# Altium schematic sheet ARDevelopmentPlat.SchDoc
size A3
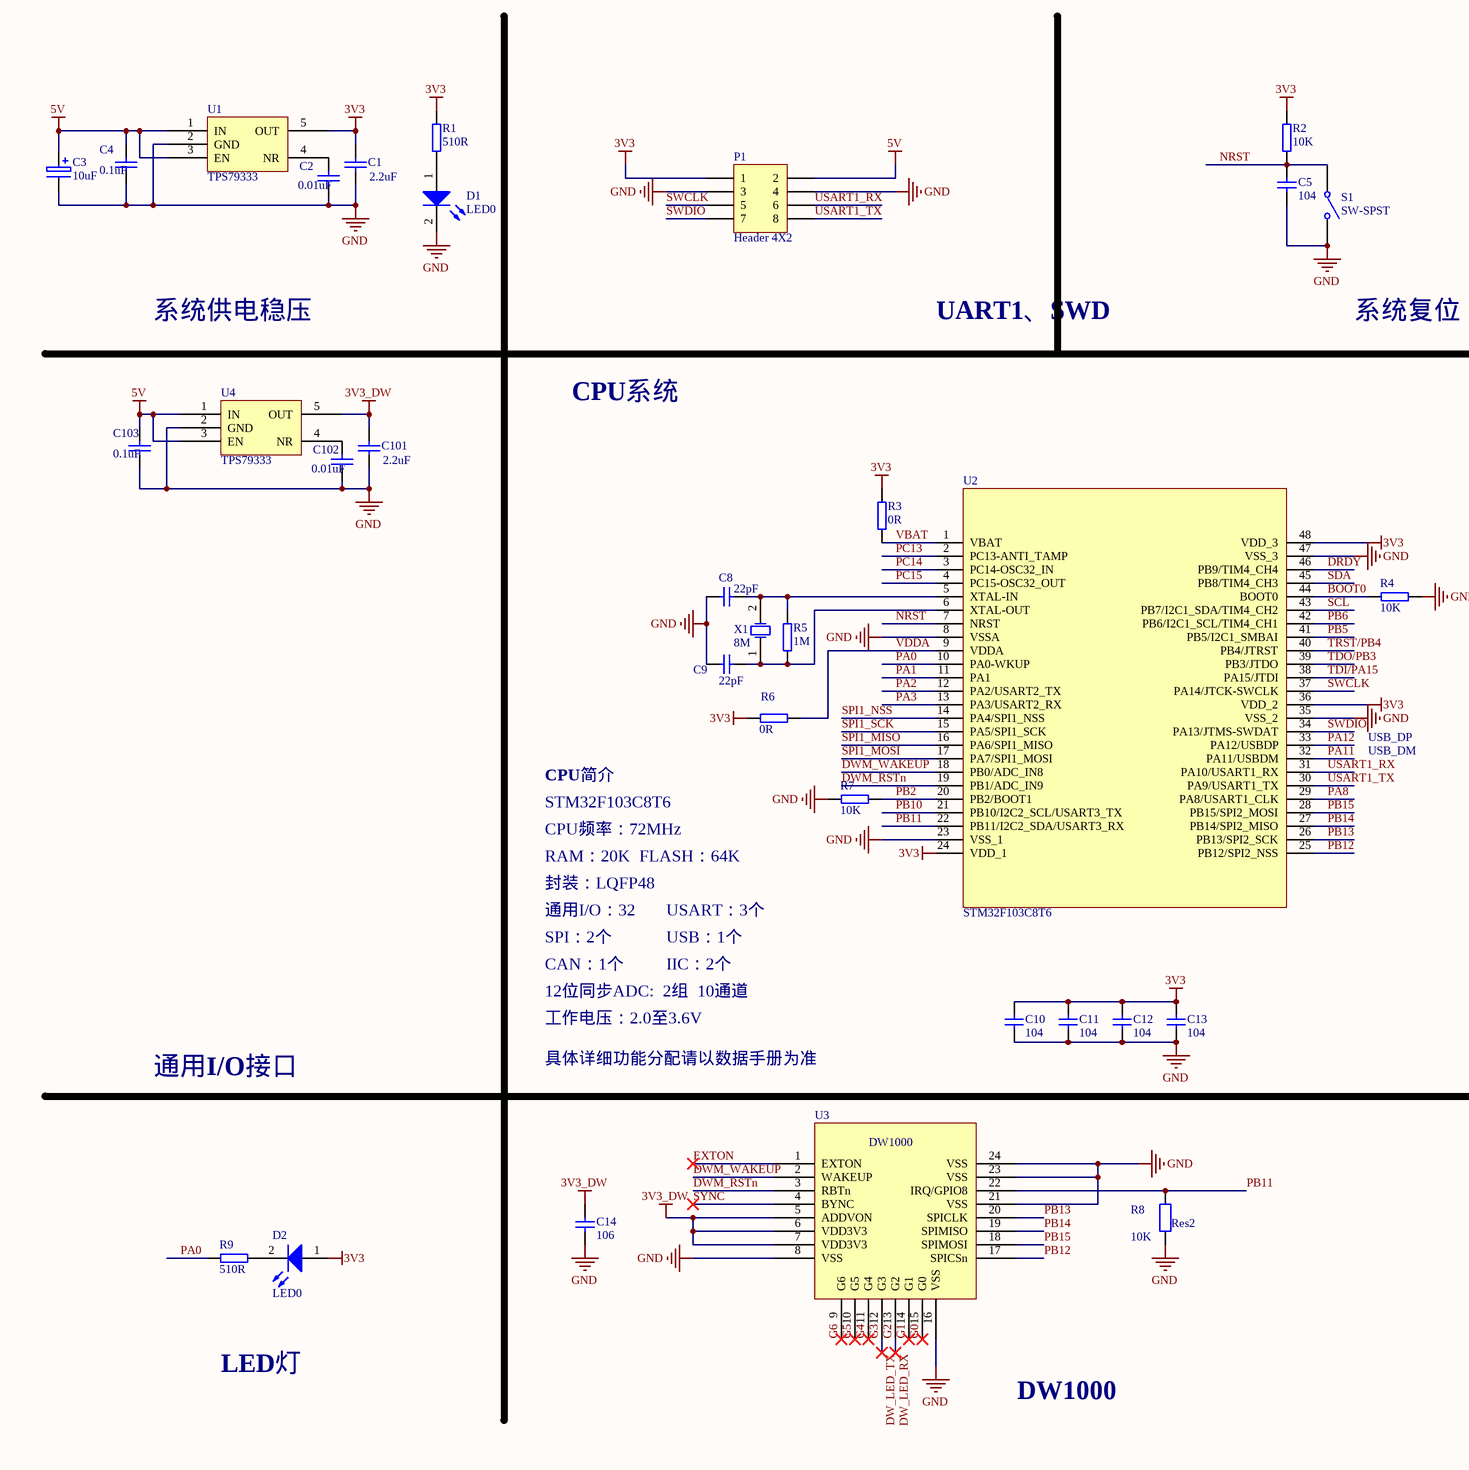
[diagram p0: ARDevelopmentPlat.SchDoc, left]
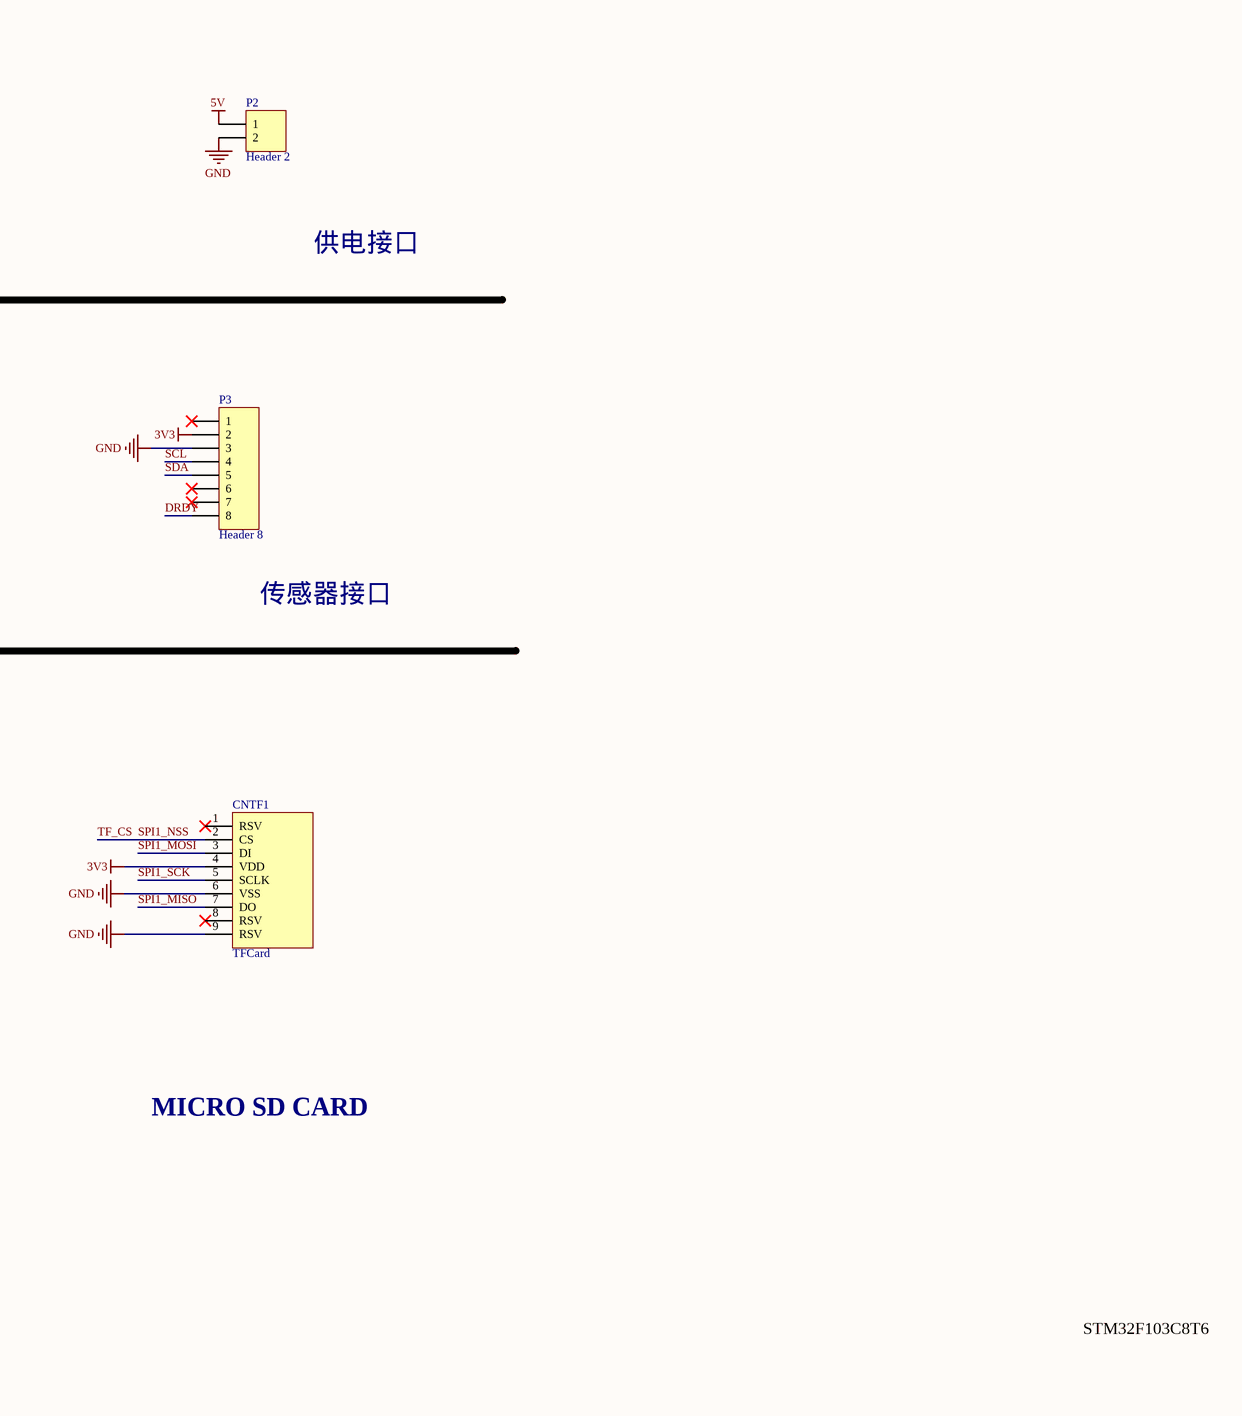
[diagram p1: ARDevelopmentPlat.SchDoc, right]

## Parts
C1  value 2.2uF  [RC0603]  (hidden comment: Cap)
C2  value 0.01uF  [RC0603]  (hidden comment: Cap)
C3  10uF  [RC0805]
C4  value 0.1uF  [RC0603]  (hidden comment: Cap)
C5  104  [RC0603]
C8  22pF  [RC0603]
C9  22pF  [RC0603]
C10  104  [RC0603]
C11  104  [RC0603]
C12  104  [RC0603]
C13  104  [RC0603]
C14  106  [RC0805]
C101  value 2.2uF  [RC0603]  (hidden comment: Cap)
C102  value 0.01uF  [RC0603]  (hidden comment: Cap)
C103  value 0.1uF  [RC0603]  (hidden comment: Cap)
CNTF1  TFCard  [MICRO SD]
D1  LED0  [LED0805]
D2  LED0  [LED0805]
P1  Header 4X2  [HDR2X4]
P2  Header 2  [HDR1X2]
P3  Header 8  [HDR1X8]
R1  510R  [RC0603]
R2  10K  [RC0603]
R3  0R  [RC0603]
R4  10K  [RC0603]
R5  1M  [RC0603]
R6  0R  [RC0603]
R7  10K  [RC0603]
R8  Res2  value 10K  [RC0603]
R9  510R  [RC0603]
S1  SW-SPST  [SMT-KEY]
U1  TPS79333  [SOT-23-5]
U2  STM32F103C8T6  [LQFP48]
U3  DW1000  [DWM1000]
U4  TPS79333  [SOT-23-5]
X1  8M  [SMD5032]

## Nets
3V3: C1.2 C10.1 C11.1 C12.1 C13.1 CNTF1.4(VDD) D2.1(A) P1.1 P3.2 R1.2 R2.2 R3.2 R6.2 U1.5(OUT) U2.24(VDD_1) U2.36(VDD_2) U2.48(VDD_3)
3V3_DW: C14.1 C101.2 U3.5(ADDVON) U3.6(VDD3V3) U3.7(VDD3V3) U4.5(OUT)
5V: C3.1 C4.2 C103.2 P1.2 P2.1 U1.1(IN) U1.3(EN) U4.1(IN) U4.3(EN)
GND: C1.1 C2.1 C3.2 C4.1 C5.2 C8.2 C9.2 C10.2 C11.2 C12.2 C13.2 C14.2 C101.1 C102.1 C103.1 CNTF1.6(VSS) CNTF1.9(RSV) D1.2(K) P1.3 P1.4 P2.2 P3.3 R4.1 R7.2 R8.1 S1.2(NO) U1.2(GND) U2.8(VSSA) U2.23(VSS_1) U2.35(VSS_2) U2.47(VSS_3) U3.8(VSS) U3.16(VSS) U3.21(VSS) U3.23(VSS) U3.24(VSS) U4.2(GND)
BOOT0: R4.2 U2.44(BOOT0)
DRDY: P3.8 U2.46(PB9/TIM4_CH4)
DW_LED_RX: U3.13(G2)  [also labelled G2]
DW_LED_TX: U3.12(G3)  [also labelled G3]
DWM_RSTn: U2.19(PB1/ADC_IN9) U3.3(RBTn)
DWM_WAKEUP: U2.18(PB0/ADC_IN8) U3.2(WAKEUP)
EXTON: U3.1(EXTON)
G0: U3.15(G0)
G1: U3.14(G1)
G4: U3.11(G4)
G5: U3.10(G5)
G6: U3.9(G6)
NRST: C5.1 R2.1 S1.1(COMMON) U2.7(NRST)
PA0: R9.1 U2.10(PA0-WKUP)
PA1: U2.11(PA1)
PA2: U2.12(PA2/USART2_TX)
PA3: U2.13(PA3/USART2_RX)
PA8: U2.29(PA8/USART1_CLK)
PA11: U2.32(PA11/USBDM)
PA12: U2.33(PA12/USBDP)
PB2: R7.1 U2.20(PB2/BOOT1)
PB5: U2.41(PB5/I2C1_SMBAI)
PB6: U2.42(PB6/I2C1_SCL/TIM4_CH1)
PB10: U2.21(PB10/I2C2_SCL/USART3_TX)
PB11: R8.2 U2.22(PB11/I2C2_SDA/USART3_RX) U3.22(IRQ/GPIO8)
PB12: U2.25(PB12/SPI2_NSS) U3.17(SPICSn)
PB13: U2.26(PB13/SPI2_SCK) U3.20(SPICLK)
PB14: U2.27(PB14/SPI2_MISO) U3.19(SPIMISO)
PB15: U2.28(PB15/SPI2_MOSI) U3.18(SPIMOSI)
PC13: U2.2(PC13-ANTI_TAMP)
PC14: U2.3(PC14-OSC32_IN)
PC15: U2.4(PC15-OSC32_OUT)
SCL: P3.4 U2.43(PB7/I2C1_SDA/TIM4_CH2)
SDA: P3.5 U2.45(PB8/TIM4_CH3)
SPI1_MISO: CNTF1.7(DO) U2.16(PA6/SPI1_MISO)
SPI1_MOSI: CNTF1.3(DI) U2.17(PA7/SPI1_MOSI)
SPI1_NSS: CNTF1.2(CS) U2.14(PA4/SPI1_NSS)  [also labelled TF_CS]
SPI1_SCK: CNTF1.5(SCLK) U2.15(PA5/SPI1_SCK)
SWCLK: P1.5 U2.37(PA14/JTCK-SWCLK)
SWDIO: P1.7 U2.34(PA13/JTMS-SWDAT)
SYNC: U3.4(BYNC)
TDI/PA15: U2.38(PA15/JTDI)
TDO/PB3: U2.39(PB3/JTDO)
TRST/PB4: U2.40(PB4/JTRST)
USART1_RX: P1.6 U2.31(PA10/USART1_RX)
USART1_TX: P1.8 U2.30(PA9/USART1_TX)
VBAT: R3.1 U2.1(VBAT)
VDDA: R6.1 U2.9(VDDA)
NetC2_2: C2.2 U1.4(NR)
NetC8_1: C8.1 R5.2 U2.5(XTAL-IN) X1.2
NetC9_1: C9.1 R5.1 U2.6(XTAL-OUT) X1.1
NetC102_2: C102.2 U4.4(NR)
NetD1_1: D1.1(A) R1.1
NetD2_2: D2.2(K) R9.2

Not connected (* = marked no-connect by the designer): CNTF1 1(RSV)* 8(RSV)*; P3 1* 6* 7*

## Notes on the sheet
- 系统供电稳压
- UART1、SWD
- 系统复位
- 供电接口
- CPU系统
- 传感器接口
- USB_DM
- USB_DP
- STM32F103C8T6
- CPU简介
- RAM：20K
- 封装：LQFP48
- CPU频率：72MHz
- FLASH：64K
- 通用I/O：32
- SPI：2个
- USART：3个
- USB：1个
- CAN：1个
- 12位同步ADC:  2组  10通道
- 工作电压：2.0至3.6V
- IIC：2个
- 通用I/O接口
- 具体详细功能分配请以数据手册为准
- MICRO SD CARD
- LED灯
- DW1000

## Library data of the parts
C1 C2 C4 C101-C103 = Cap: Capacitor
C3 = cap_polarity2: Electrolytic Capacitor
C5 C10-C14 = CAP1: Capacitor; Tolerate: 50V; Value: 100nF; TOL: 10%; ERP: 0103020075; PCB_Layout: Top Layer SMC
C8 C9 = CAP1: Capacitor; Tolerate: 50V; Value: 20pF; TOL: 2%; ERP: 0103020090; PCB_Layout: Top Layer SMC
D1 D2 = LED0: Typical INFRARED GaAs LED
P1 = Header 4X2: Header, 4-Pin, Dual row
P2 = Header 2: Header, 2-Pin
P3 = Header 8: Header, 8-Pin
R1-R7 R9 = R
R8 = Res2: Resistor
S1 = SW-SPST: Single-Pole, Single-Throw Switch
X1 = XTAL_SMD: Crystal Oscillator; ERP: 0103040021; Value: 8MHz; TOL: ±20ppm; Tolerate: ROSON -20_+70 20pf; PCB_Layout: Top Layer SMC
